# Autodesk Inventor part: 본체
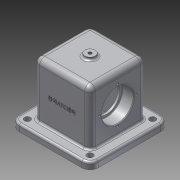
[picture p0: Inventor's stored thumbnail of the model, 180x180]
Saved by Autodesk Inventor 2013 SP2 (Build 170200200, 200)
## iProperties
Created: 2022-07
Part Number: 본체
Material: 알루미늄 6061
Document SubType Name: Modeling
Designer: aa
Density: 2.71 g/cm^3
Mass: 1064.09 g
Surface Area: 720.854 cm^2
Volume: 392.653 cm^3
Author: aa
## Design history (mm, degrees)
sketch "스케치1"
  geometry: L1 (58, -58)-(-58, -58); L2 (-58, -58)-(-58, 58); L3 (-58, 58)-(58, 58); L4 (58, 58)-(58, -58); L5 (58, -58)-(-58, 58); L6 (-58, -58)-(58, 58); 1 further point
  constraints: 12 end point, 2 midpoint, 2 parallel, 1 horizontal, 1 perpendicular
  dimensions: "d0" = 116 distance of L2.end L3.end; "d1" = 116 distance of L1.end L2.end
extrude "돌출1" new body sketch "스케치1" distance "d2" = 10; taper "d3" = 0 deg
sketch "스케치2"
  geometry: L1 (-41, -41)-(41, -41); L2 (41, -41)-(41, 41); L3 (41, 41)-(-41, 41); L4 (-41, 41)-(-41, -41); L5 (-41, -41)-(41, 41); L6 (41, -41)-(-41, 41); 1 further point
  constraints: 12 end point, 2 midpoint, 2 parallel, 1 horizontal, 1 perpendicular
  dimensions: "d4" = 82 distance of L3.end L2.end; "d5" = 82 distance of L2.end L1.end
extrude "돌출2" join sketch "스케치2" distance "d6" = 80; taper "d7" = 0 deg
sketch "스케치3"
  geometry: C1 r 7.5 at (0, 0); 1 further point
  constraints: 1 centre point, 1 coincident
  dimensions: "d8" = 15 diameter of C1
extrude "돌출3" join sketch "스케치3" distance "d9" = 4; taper "d10" = 0 deg
sketch "스케치5"
  geometry: L1 (-21, 30)-(21, 30); L2 (21, 30)-(21, -30); L3 (21, -30)-(-21, -30); L4 (-21, -30)-(-21, 30); L5 (-21, 30)-(21, -30); L6 (21, 30)-(-21, -30); 1 further point
  constraints: 12 end point, 2 midpoint, 2 parallel, 1 horizontal, 1 perpendicular
  dimensions: "d19" = 42 distance of L2.end L3.end; "d20" = 60 distance of L1.end L2.end
extrude "돌출4" cut sketch "스케치5" distance "d21" = 80; taper "d22" = 0 deg
sketch "스케치6"
  geometry: C1 r 7.5 at (0, 0) reference; 1 further point
  constraints: 1 coincident
hole "구멍1" sketch "스케치6" at (0, 0) diameter "d23" = 4.917; stored, may be unused: countersink angle "d27" = 90 deg, drill point angle "d29" = 118 deg; dims "d24" = 20, "d25" = 4, "d26" = 2, "d28" = 22
sketch "스케치7"
  geometry: L1 (0, 0)-(0, 48); L2 (-41, 10)-(-41, 90) reference; L3 (41, 10)-(41, 90) reference; L4 (-41, 48)-(41, 48); L5 (-41, 48)-(-41, 71.5); L6 (-41, 71.5)-(-24, 71.5); L7 (-24, 71.5)-(-24, 68); L8 (-24, 68)-(24, 68); L9 (24, 68)-(24, 71.5); L10 (24, 71.5)-(41, 71.5); L11 (41, 48)-(41, 71.5)
  constraints: 18 end point, 4 perpendicular, 4 point on line, 2 parallel, 1 collinear, 1 vertical
  dimensions: "d30" = 48 distance of L1.start L1.end; "d31" = 47 diameter of L6 L4; "d32" = 40 diameter of L8 L4; "d33" = 17 distance of L5.end L6.end; "d34" = 17 distance of L9.end L10.end; "d35" = 47 diameter of L10 L4; "d36" = 48 vertical distance of L1.start L4.end
revolve "회전1" sketch "스케치7" stored, may be unused: angle "d37" = 90 deg
fillet "모깎기1" dims "d38" = 12
sketch "스케치8"
  geometry: A1 r 12 centre (-46, 46) between (-46, 58) and (-58, 46) reference; A2 r 12 centre (-46, -46) between (-58, -46) and (-46, -58) reference; A3 r 12 centre (46, -46) between (46, -58) and (58, -46) reference; A4 r 12 centre (46, 46) between (58, 46) and (46, 58) reference; 5 further points
  constraints: 4 coincident
hole "구멍2" sketch "스케치8" at (-46, 46), (46, 46), (46, -46), (-46, -46) diameter "d39" = 9; stored, may be unused: countersink angle "d43" = 90 deg, drill point angle "d45" = 118 deg; dims "d40" = 10, "d41" = 4, "d42" = 2, "d44" = 12
sketch "스케치9"
  geometry: C1 r 23.5 at (41, 38) reference; A1 r 27 centre (41, 38) between (41, 65) and (41, 11); 3 further points
  constraints: 4 point on circle, 2 horizontal alignment, 2 vertical alignment, 1 centre point, 1 coincident
  dimensions: "d46" = 54 diameter of A1
hole "구멍3" sketch "스케치9" at (41, 65), (41, 11), (14, 38), (68, 38) diameter "d47" = 3.242; stored, may be unused: countersink angle "d51" = 90 deg, drill point angle "d53" = 118 deg; dims "d48" = 8, "d49" = 4, "d50" = 2, "d52" = 10
fillet "모깎기2" dims "d54" = 3
fillet "모깎기3" dims "d55" = 8
fillet "모깎기4" dims "d56" = 8
fillet "모깎기5" dims "d57" = 3
chamfer "모따기1" distance "d58" = 1; stored, may be unused: second distance "d59" = 2, angle "d60" = 45 deg
fillet "모깎기6" dims "d61" = 3
fillet "모깎기7" dims "d62" = 3
sketch "스케치10"
  geometry: L1 (79, -82)-(-13, -82) reference; 3 further points
  constraints: 1 midpoint, 1 vertical alignment, 1 other
  dimensions: "d63" = 48 distance from line of point (33, -34) L1
feature "엠보싱1" sketch "스케치10" dims "d0" = 116, "d1" = 116, "d64" = 0.5, "d65" = 0
fillet "모깎기8" dims "d66" = 0.6
node "솔리드1"
mirror "대칭1"
